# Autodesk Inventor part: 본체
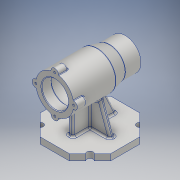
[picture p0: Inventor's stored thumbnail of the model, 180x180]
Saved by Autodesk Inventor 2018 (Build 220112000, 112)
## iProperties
Created: 2019-12
Part Number: 본체
Material: 알루미늄 6061
Document SubType Name: Modeling
Designer: Administrator
Density: 2.70108 g/cm^3
Appearance: 알루미늄 - 평지
Mass: 734 g
Surface Area: 721.545 cm^2
Volume: 271.743 cm^3
Author: Administrator
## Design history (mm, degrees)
sketch "스케치1"
  geometry: L1 (56, -23.196)-(23.196, -56); L2 (23.196, -56)-(-23.196, -56); L3 (-23.196, -56)-(-56, -23.196); L4 (-56, -23.196)-(-56, 23.196); L5 (-56, 23.196)-(-23.196, 56); L6 (-23.196, 56)-(23.196, 56); L7 (23.196, 56)-(56, 23.196); L8 (56, 23.196)-(56, -23.196); L9 (39.598, 39.598)-(0, 0); L10 (0, 0)-(56, 0); A1 r 56 centre (0, 0) between (39.598, 39.598) and (56, 0); 6 further points
  constraints: 20 end point, 2 coincident, 2 point on circle, 1 centre point, 1 horizontal, 1 midpoint, 1 vertical alignment, 22 other
  dimensions: "d0" = 56 distance from line of L8 point (0, 0); "d1" = 45 deg angle of L10 L9; "d4" = 360 deg dimension on point (0, 0) L9.start (derived); "d6" = 112 diameter of A1
extrude "돌출1" new body sketch "스케치1" distance "d7" = 10; taper "d8" = 0 deg
hole "구멍1" sketch "스케치1" diameter "d9" = 10; stored, may be unused: countersink angle "d13" = 90 deg, drill point angle "d15" = 118 deg; dims "d10" = 6, "d11" = 4, "d12" = 2, "d14" = 8
sketch "스케치2"
  geometry: L1 (43.134, 10)-(56, 10) reference; L2 (36, 10)-(6.882, 90); L3 (6.882, 90)-(0, 90); L4 (0, 90)-(0, 10); L5 (-23.196, 10)-(23.196, 10) reference; L6 (36, 10)-(0, 10); L7 (56, 0)-(56, 10) reference; 1 further point
  constraints: 8 end point, 1 collinear, 1 midpoint, 1 parallel, 1 point on line
  dimensions: "d16" = 20 distance from line of L7 L2.start; "d17" = 110 deg angle of L2 L1; "d18" = 80 distance between parallel lines of L5 L3
extrude "돌출2" join sketch "스케치2" stored distance "d19" = 8; taper "d20" = 0 deg
sketch "스케치3"
  geometry: L1 (38, 10)-(5.358, 80); L2 (5.358, 80)-(-31, 80); L3 (34.598, 10)-(43.134, 10) reference; L4 (-31, 80)-(-31, 10); L5 (-43.134, 10)-(-56, 10) reference; L6 (-31, 10)-(38, 10); L7 (43.134, 0)-(43.134, 10) reference; L8 (-56, 0)-(-56, 10) reference; L9 (56, 0)-(56, 10) reference; L10 (56, 10)-(43.134, 10) reference; L11 (-23.196, 0)-(23.196, 0) reference; 2 further points
  constraints: 8 end point, 2 perpendicular, 1 parallel, 1 point on line
  dimensions: "d21" = 25 distance between parallel lines of L8 L4; "d22" = 18 distance from line of L9 L1.start; "d23" = 115 deg angle of L10 L1; "d24" = 80 distance between parallel lines of L11 L2
extrude "돌출3" join sketch "스케치3" stored distance "d25" = 8; taper "d26" = 0 deg
sketch "스케치4"
  geometry: L1 (-56, 80)-(11, 80); L2 (11, 80)-(11, 110); L3 (11, 110)-(-56, 110); L4 (-56, 110)-(-56, 80); L5 (31, 80)-(56, 80); L6 (56, 80)-(56, 105); L7 (56, 105)-(31, 105); L8 (31, 105)-(31, 80); L9 (11, 110)-(31, 105); L10 (11, 80)-(31, 80); L11 (23.196, 0)-(-23.196, 0) reference; 2 further points
  constraints: 20 end point, 4 parallel, 2 horizontal, 2 perpendicular, 1 collinear, 1 point on line, 1 vertical alignment
  dimensions: "d27" = 60 diameter of L3 L1; "d28" = 50 diameter of L7 L5; "d29" = 25 distance between parallel lines of L6 L8; "d30" = 45 distance between parallel lines of L2 L6; "d31" = 112 distance between parallel lines of L6 L4; "d32" = 80 distance between parallel lines of L11 L1
revolve "회전1" sketch "스케치4" stored, may be unused: angle "d33" = 90 deg
sketch "스케치5"
  geometry: L1 (-56, 50)-(-56, 110) reference; L2 (-56, 80)-(-41, 80); L3 (-41, 80)-(-41, 101); L4 (-41, 101)-(-56, 101); L5 (-56, 101)-(-56, 80); L6 (-41, 80)-(13, 80); L7 (13, 80)-(13, 101); L8 (10, 104)-(-38, 104); L9 (-41, 101)-(-41, 80); L10 (13, 80)-(25, 80); L11 (25, 80)-(25, 100.7); L12 (13, 101)-(13, 80); L13 (25, 80)-(43, 80); L14 (43, 80)-(43, 97.2); L15 (42.7, 97.5)-(25, 97.5); L16 (25, 97.5)-(25, 80); L17 (43, 80)-(47, 80); L18 (47, 80)-(47, 95.7); L19 (46.7, 96)-(43, 96); L20 (43, 96)-(43, 80); L21 (47, 80)-(50, 80); L22 (50, 80)-(50, 90.5); L23 (50, 90.5)-(47, 90.5); L24 (47, 90.5)-(47, 80); L25 (24.7, 101)-(13, 101); L26 (11, 50.268)-(11, 110) reference; A1 r 3 centre (-38, 101) between (-38, 104) and (-41, 101); A2 r 3 centre (10, 101) between (13, 101) and (10, 104); A3 r 0.3 centre (24.7, 100.7) between (25, 100.7) and (24.7, 101); A4 r 0.3 centre (42.7, 97.2) between (43, 97.2) and (42.7, 97.5); A5 r 0.3 centre (46.7, 95.7) between (47, 95.7) and (46.7, 96); 6 further points
  constraints: 48 end point, 11 parallel, 11 point on line, 10 point on circle, 10 tangent, 7 perpendicular, 6 horizontal, 5 centre point, 3 equal radius, 1 midpoint
  dimensions: "d34" = 42 diameter of L4 L2; "d35" = 48 diameter of L8 L6; "d36" = 35 diameter of L15 L13; "d37" = 32 diameter of L19 L17; "d38" = 21 diameter of L23 L21; "d39" = 15 distance of L3.end L4.end; "d40" = 54 distance of point (13, 104) point (-41, 104); "d41" = 12 distance of point (25, 101) L12.start; "d42" = 18 distance of point (43, 97.5) L15.end; "d43" = 3 distance of L22.end L23.end; "d44" = 4 distance of point (47, 96) L19.end; "d70" = 3 radius of A1; "d71" = 0.3 radius of A3
revolve "회전2" sketch "스케치5" stored, may be unused: angle "d45" = 90 deg
sketch "스케치6"
  geometry: C1 r 6 at (0, 30); A1 r 30 centre (0, 0) between (4, -29.732) and (-4, -29.732) reference; 1 further point
  constraints: 1 centre point, 1 point on circle
  dimensions: "d46" = 12 diameter of C1
extrude "돌출4" join sketch "스케치6" distance "d47" = 16; taper "d48" = 0 deg
sketch "스케치7" dims "d49" = 60
  geometry: A1 r 30 centre (0, -30) between (4, -59.732) and (-4, -59.732) reference; 3 further points
  constraints: 1 coincident, 1 vertical alignment, 2 other
hole "구멍2" sketch "스케치7" at (0, 0) diameter "d50" = 3.242; stored, may be unused: countersink angle "d54" = 90 deg, drill point angle "d56" = 118 deg; dims "d51" = 8, "d52" = 4, "d53" = 2, "d55" = 11
fillet "모깎기1" dims "d60" = 3
fillet "모깎기2" dims "d61" = 3
fillet "모깎기3" dims "d62" = 3
fillet "모깎기4" dims "d63" = 3
fillet "모깎기5" dims "d64" = 3
fillet "모깎기6" dims "d65" = 1
fillet "모깎기7" dims "d69" = 3
chamfer "모따기1" distance "d72" = 1; stored, may be unused: second distance "d73" = 2, angle "d74" = 45 deg
node "작업 평면1"
sketch "스케치8"
  geometry: L1 (56, 55)-(56, 105) reference; L2 (-56, 86.771)-(-56, 109.226) reference; 3 further points
  constraints: 1 midpoint, 1 other
feature "엠보싱1" sketch "스케치8" dims "d0" = 56, "d1" = 45 deg, "d4" = 360 deg (derived), "d6" = 112, "d77" = 0.5, "d78" = 0
node "솔리드1"
mirror "미러1"
pattern_circular "원형 패턴1" dims angle "d58" = 360 deg
pattern_circular "원형 패턴2" dims angle "d67" = 360 deg
